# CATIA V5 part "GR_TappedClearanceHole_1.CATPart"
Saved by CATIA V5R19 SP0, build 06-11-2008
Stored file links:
  C:\Program Files\Dassault Systemes\Power Feature\SampleData\GeneralData\GeometricalRules\GeomRuleParts\GR_TappedClearanceHole_1.CATPart
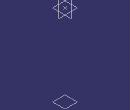
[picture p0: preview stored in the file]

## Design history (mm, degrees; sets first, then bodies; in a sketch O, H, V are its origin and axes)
Set1
  Point1: (0, 0, 0)
  Plane1: type Offset, RefPlane xy-plane
Body1 (main body)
